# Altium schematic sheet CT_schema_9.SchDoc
size 274 x 160 mm
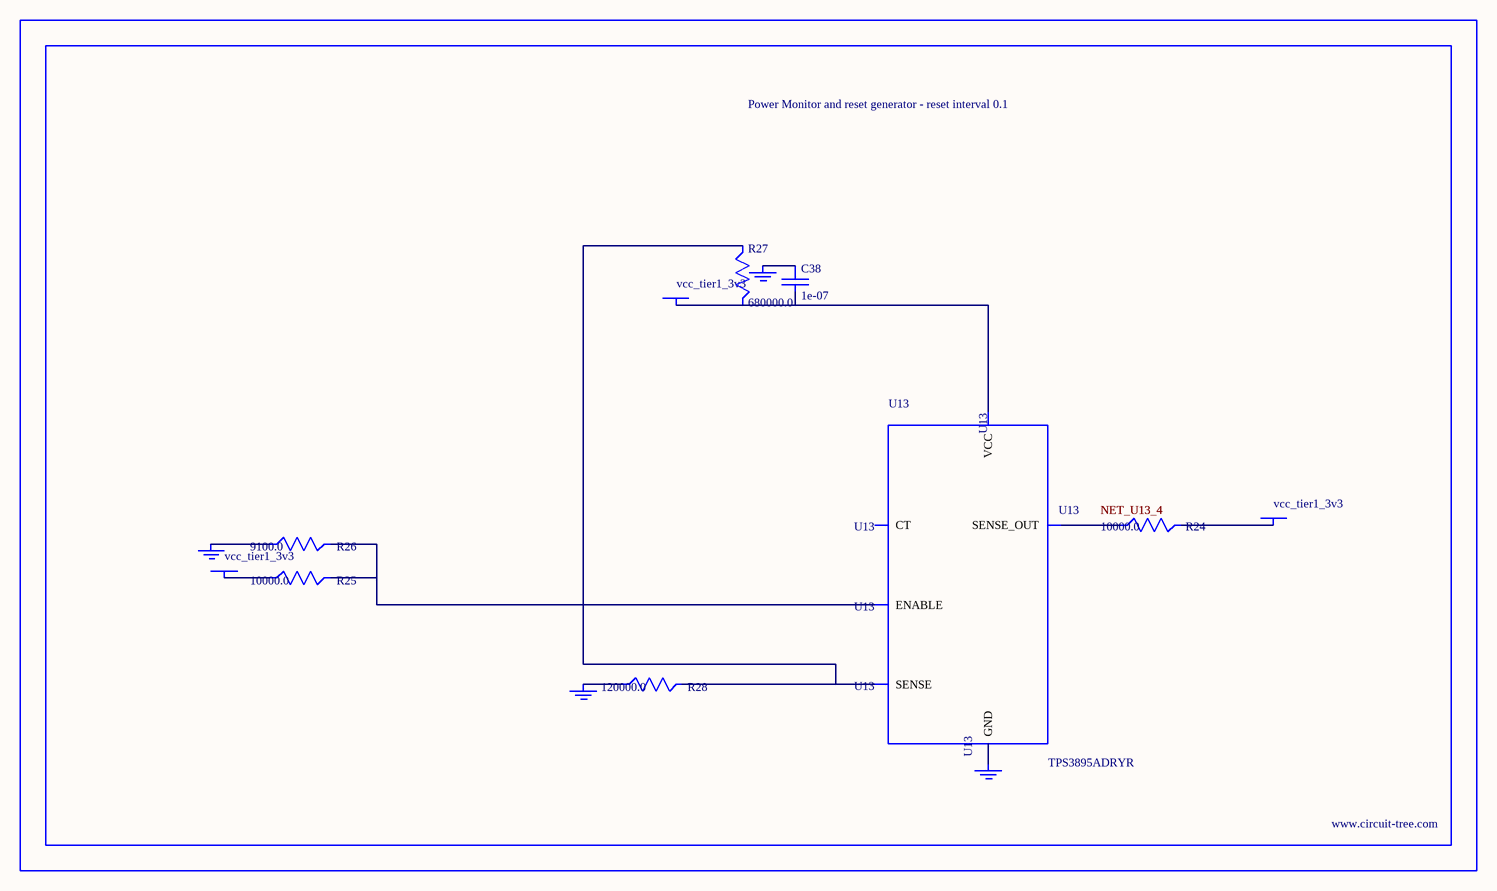
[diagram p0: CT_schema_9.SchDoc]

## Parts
BORDER8  (no value)
C38  1e-07  [C0402]
GND_INSTANCE_8_0  (no value)
GND_INSTANCE_8_1  (no value)
GND_INSTANCE_8_2  (no value)
GND_INSTANCE_8_3  (no value)
POWER_INSTANCE_8_0  vcc_tier1_3v3
POWER_INSTANCE_8_1  vcc_tier1_3v3
POWER_INSTANCE_8_2  vcc_tier1_3v3
R24  10000.0  [R0603]
R25  10000.0  [R0603]
R26  9100.0  [R0603]
R27  680000.0  [R0603]
R28  120000.0  [R0603]
U13  TPS3895ADRYR  [SON-6]

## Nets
NetC38_1: C38.1 GND_INSTANCE_8_2.0(GND)
NetC38_2: C38.2 POWER_INSTANCE_8_2.0(PWR) R27.2 U13.6(VCC)
NetGND_INSTANCE_8_0_0: GND_INSTANCE_8_0.0(GND) R26.1
NetGND_INSTANCE_8_1_0: GND_INSTANCE_8_1.0(GND) R28.1
NetGND_INSTANCE_8_3_0: GND_INSTANCE_8_3.0(GND) U13.2(GND)
NetPOWER_INSTANCE_8_0_0: POWER_INSTANCE_8_0.0(PWR) R25.1
NetPOWER_INSTANCE_8_1_0: POWER_INSTANCE_8_1.0(PWR) R24.2
NetR24_1: R24.1 U13.4(SENSE_OUT)
NetR25_2: R25.2 R26.2 U13.1(ENABLE)
NetR27_1: R27.1 R28.2 U13.3(SENSE)

Not connected (* = marked no-connect by the designer): U13 5(CT)

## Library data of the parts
BORDER8 = BORDER_PAGE8
C38 = C0402C104K3RACTU
GND_INSTANCE_8_0-GND_INSTANCE_8_3 = GND
POWER_INSTANCE_8_0-POWER_INSTANCE_8_2 = PWR
R24 R25 = RC0603JR-0710KL
R26 = RC0603JR-079K1L
R27 = RC0603JR-07680KL
R28 = RC0603JR-07120KL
